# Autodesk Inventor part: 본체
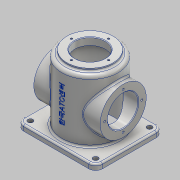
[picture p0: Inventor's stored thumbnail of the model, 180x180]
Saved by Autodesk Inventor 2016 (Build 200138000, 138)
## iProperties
Created: 2021-02
Part Number: 본체
Material: 알루미늄 6061
Document SubType Name: Modeling
Designer: user
Density: 2.7 g/cm^3
Appearance: 알루미늄 - 평지
Mass: 1235.14 g
Surface Area: 1068.45 cm^2
Volume: 457.459 cm^3
Author: user
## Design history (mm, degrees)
sketch "스케치1"
  geometry: L1 (-70, 60)-(70, 60); L2 (70, 60)-(70, -60); L3 (70, -60)-(-70, -60); L4 (-70, -60)-(-70, 60); L5 (-70, 60)-(70, -60); L6 (70, 60)-(-70, -60); 1 further point
  constraints: 12 end point, 2 midpoint, 2 parallel, 1 horizontal, 1 perpendicular
  dimensions: "d0" = 140 distance of L2.end L3.end; "d1" = 120 distance of L1.end L2.end
extrude "돌출1" new body sketch "스케치1" distance "d2" = 10; taper "d3" = 0 deg
fillet "모깎기1" dims "d4" = 12
hole "구멍1" diameter "d7" = 9; stored, may be unused: countersink angle "d11" = 90 deg, drill point angle "d13" = 118 deg; dims "d5" = 10, "d6" = 10, "d8" = 6, "d9" = 4, "d10" = 2, "d12" = 8
sketch "스케치2"
  geometry: C1 r 50 at (0, 0); 1 further point
  constraints: 1 centre point, 1 coincident
  dimensions: "d20" = 100 diameter of C1
extrude "돌출2" join sketch "스케치2" distance "d21" = 110; taper "d22" = 0 deg
sketch "스케치3"
  geometry: C1 r 41 at (0, 0); 1 further point
  constraints: 1 centre point, 1 coincident
  dimensions: "d23" = 82 diameter of C1
extrude "돌출3" join sketch "스케치3" distance "d24" = 5; taper "d25" = 0 deg
sketch "스케치5"
  geometry: 2 further points
  constraints: 1 coincident
hole "구멍2" sketch "스케치5" at (0, 0) diameter "d27" = 54; stored, may be unused: countersink angle "d31" = 90 deg, drill point angle "d33" = 118 deg; dims "d28" = 6, "d29" = 84, "d30" = 112, "d32" = 125
node "작업 평면1"
sketch "스케치6"
  geometry: L1 (50, 120)-(-50, 120) reference; L2 (-50, 10)-(50, 10) reference; L3 (48, 0)-(-48, 0) reference; L4 (48, 10)-(48, 0) reference; L5 (-48, 10)-(48, 10) reference; L6 (-48, 0)-(-48, 10) reference; L7 (48, 0)-(-48, 0) reference; C1 r 41 at (0, 60.02); 2 further points
  constraints: 1 centre point, 1 midpoint, 1 vertical alignment
  dimensions: "d35" = 82 diameter of C1; "d36" = 60.02 distance from line of C1.centre L3
extrude "돌출4" join sketch "스케치6" stored distance "d37" = 5; taper "d38" = 0 deg
hole "구멍3" diameter "d41" = 54; stored, may be unused: countersink angle "d45" = 90 deg, drill point angle "d47" = 118 deg; dims "d39" = 10, "d40" = 10, "d42" = 6, "d43" = 84, "d44" = 112, "d46" = 125
chamfer "모따기1" distance "d48" = 1; stored, may be unused: second distance "d49" = 2, angle "d50" = 45 deg
chamfer "모따기2" distance "d51" = 1; stored, may be unused: second distance "d52" = 2, angle "d53" = 45 deg
sketch "스케치7"
  geometry: L1 (-60.02, -48)-(-60.02, 48) reference; L2 (0, 0)-(33, 0); C1 r 41 at (0, 0) reference; C2 r 28 at (0, 0) reference; 1 further point
  constraints: 2 end point, 1 horizontal
  dimensions: "d54" = 33 distance of L2.start L2.end
hole "구멍4" sketch "스케치7" at (33, 0) diameter "d55" = 3.459; stored, may be unused: countersink angle "d59" = 90 deg, drill point angle "d61" = 118 deg; dims "d56" = 8, "d57" = 84, "d58" = 112, "d60" = 10
fillet "모깎기2" dims "d65" = 6
fillet "모깎기3" dims "d66" = 3
fillet "모깎기4" dims "d67" = 3
fillet "모깎기5" dims "d68" = 3
fillet "모깎기6" dims "d69" = 3
fillet "모깎기7" dims "d70" = 3
sketch "스케치8"
  geometry: L1 (0, 0)-(33, 0); C1 r 41 at (0, 0) reference; C2 r 28 at (0, 0) reference; 1 further point
  constraints: 2 end point, 1 horizontal
  dimensions: "d71" = 33 distance of L1.start L1.end
hole "구멍5" sketch "스케치8" at (33, 0) diameter "d72" = 3.459; stored, may be unused: countersink angle "d76" = 90 deg, drill point angle "d78" = 118 deg; dims "d73" = 8, "d74" = 84, "d75" = 112, "d77" = 10
node "작업 평면3"
sketch "스케치9"
  geometry: L1 (58, 0)-(-58, 0) reference; 3 further points
  constraints: 1 midpoint, 1 vertical alignment, 1 other
  dimensions: "d83" = 66 distance from line of point (0, 66) L1
feature "엠보싱1" sketch "스케치9" dims "d0" = 140, "d1" = 120, "d84" = 0.5, "d85" = 0
node "솔리드1"
pattern_linear "직사각형 패턴1" dims "d16" = 116, "d19" = 96
mirror "대칭1"
pattern_circular "원형 패턴1" dims angle "d63" = 360 deg
mirror "대칭2"
pattern_circular "원형 패턴2" dims angle "d80" = 360 deg
node "투영된 루프1"
node "투영된 루프2"
node "작업 평면2"
node "투영된 루프3"
node "투영된 루프4"
other parameters: "d34" = 59
